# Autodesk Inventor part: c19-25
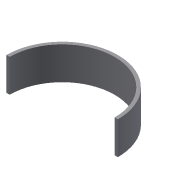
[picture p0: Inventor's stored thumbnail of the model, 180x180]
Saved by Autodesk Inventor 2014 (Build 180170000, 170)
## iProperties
Created: 2013-07
Part Number: c19-25
Material: Generic
Document SubType Name: Modeling
Designer: CADCIM
Density: 1 g/cm^3
Appearance: Default
Author: CADCIM
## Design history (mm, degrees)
sketch "Sketch1"
  geometry: L1 (-17, 0)-(-16, 0); L2 (16, 0)-(17, 0); A1 r 17 centre (0, 0) between (17, 0) and (-17, 0); A2 r 16 centre (0, 0) between (16, 0) and (-16, 0); 1 further point
  constraints: 4 end point, 4 point on circle, 2 centre point, 2 coincident
extrude "Extrusion1" new body sketch "Sketch1" distance "d0" = 10; taper "d1" = 0 deg
body "Solid1"
